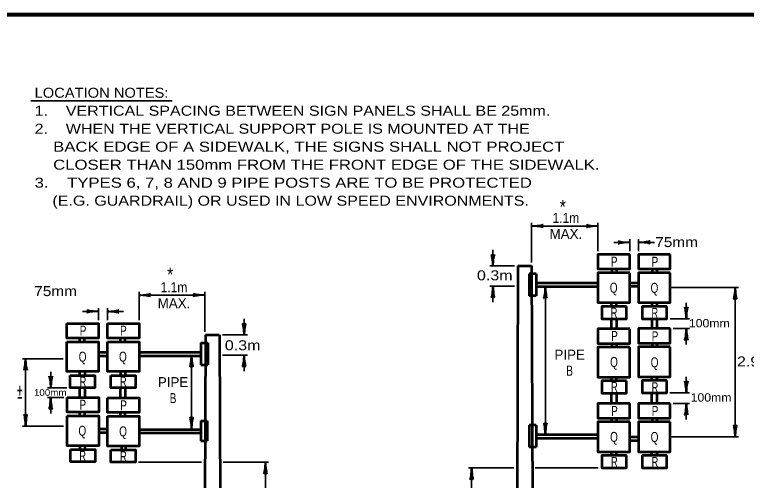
# Model space of a CAD drawing. Extents: x -274 to 582, y -298 to 246.
# Drawn here: x -65.4 to 154.4, y 100.2 to 240 of the extents above; entities that cross this region are included whole.
import ezdxf
from ezdxf.enums import TextEntityAlignment as Align

# ---------------------------------------------------------------- set-up
doc = ezdxf.new("R2010")
doc.units = 0
doc.header["$LTSCALE"] = 1.2
doc.layers.add('1', color=7, linetype='Continuous', lineweight=53)

msp = doc.modelspace()

# ---------------------------------------------------------------- linework, layer by layer
at = {"layer": '1', "lineweight": 35}
for p, q in [((-60.569, 214.078), (-18.056, 214.078)), ((89.842, 165.522), (89.842, 177.471)), ((109.785, 176.513), (89.842, 176.513)), ((109.785, 168.966), (109.785, 177.471)), ((119.321, 171.618), (114.529, 171.618)), ((119.321, 168.966), (119.321, 172.576)), ((121.978, 168.966), (121.978, 172.576)), ((126.769, 171.618), (121.978, 171.618)), ((78.241, 169.355), (78.241, 164.563)), ((84.76, 164.563), (77.282, 164.563)), ((84.76, 158.494), (77.282, 158.494)), ((78.241, 158.494), (78.241, 153.702)), ((93.996, 158.284), (93.996, 113.897)), ((-27.98, 148.24), (-27.98, 156.746)), ((-8.292, 144.796), (-8.292, 156.746)), ((131.513, 158.023), (151.957, 158.023)), ((150.999, 158.023), (150.999, 113.28)), ((-28.023, 155.787), (-8.292, 155.787)), ((-40.215, 148.24), (-40.215, 151.85)), ((-37.558, 148.24), (-37.558, 151.85)), ((136.326, 153.5), (136.326, 148.708)), ((-45.006, 150.892), (-40.215, 150.892)), ((-37.558, 150.892), (-32.766, 150.892)), ((3.522, 148.629), (3.522, 143.838)), ((131.462, 148.708), (137.284, 148.708)), ((132.407, 145.762), (137.284, 145.762)), ((136.326, 145.762), (136.326, 140.97)), ((-2.997, 143.838), (4.481, 143.838)), ((-63.006, 136.7), (-50.809, 136.7)), ((-62.135, 136.7), (-62.135, 116.476)), ((-12.29, 137.758), (-12.29, 115.671)), ((-2.997, 137.768), (4.481, 137.768)), ((3.522, 137.768), (3.522, 132.977)), ((-54.563, 132.774), (-54.563, 127.983)), ((136.326, 131.254), (136.326, 126.462)), ((-49.699, 127.983), (-55.521, 127.983)), ((131.398, 126.462), (137.284, 126.462)), ((-50.644, 125.036), (-55.521, 125.036)), ((-54.563, 125.036), (-54.563, 120.244)), ((132.407, 123.265), (137.284, 123.265)), ((136.326, 123.265), (136.326, 118.473)), ((-63.006, 116.476), (-50.752, 116.476)), ((131.449, 113.28), (151.957, 113.28)), ((-28.188, 105.611), (-9.269, 105.611)), ((-2.808, 105.611), (10.824, 105.611)), ((9.93, 105.611), (9.93, 70.015)), ((84.507, 103.928), (70.875, 103.928)), ((71.833, 103.928), (71.833, 68.332)), ((109.887, 103.928), (90.968, 103.928))]:
    msp.add_line(p, q, dxfattribs=at)
at = {"layer": '1'}
for p, q in [((85.718, 164.563), (85.452, 68.332)), ((85.718, 164.563), (89.842, 164.563)), ((89.842, 164.563), (90.241, 68.332)), ((114.005, 162.511), (114.005, 163.632)), ((115.426, 162.511), (115.426, 163.632)), ((126.197, 162.511), (126.197, 163.632)), ((127.618, 162.511), (127.618, 163.632)), ((91.237, 162.207), (89.142, 162.207)), ((89.142, 162.207), (89.142, 155.606)), ((91.237, 162.207), (91.237, 155.606)), ((109.746, 159.399), (91.237, 159.399)), ((109.746, 158.284), (91.237, 158.284)), ((122.068, 159.356), (119.411, 159.356)), ((122.068, 158.329), (119.411, 158.329)), ((91.237, 155.606), (89.142, 155.606)), ((113.845, 152.411), (113.845, 153.535)), ((115.394, 152.411), (115.394, 153.535)), ((126.037, 152.411), (126.037, 153.535)), ((127.586, 152.411), (127.586, 153.535)), ((113.877, 145.637), (113.877, 148.583)), ((115.426, 145.637), (115.426, 148.583)), ((126.037, 145.762), (126.037, 148.708)), ((127.586, 145.762), (127.586, 148.708)), ((-45.855, 141.785), (-45.855, 142.906)), ((-44.434, 141.785), (-44.434, 142.906)), ((-33.663, 141.785), (-33.663, 142.906)), ((-32.242, 141.785), (-32.242, 142.906)), ((-8.14, 143.838), (-8.345, 70.015)), ((-8.079, 143.838), (-3.955, 143.838)), ((-3.862, 143.838), (-3.556, 70.015)), ((-9.474, 141.482), (-7.379, 141.482)), ((-9.474, 141.482), (-9.474, 134.88)), ((-7.379, 141.482), (-7.379, 134.88)), ((114.005, 140.139), (114.005, 141.26)), ((115.426, 140.139), (115.426, 141.26)), ((126.133, 140.264), (126.133, 141.385)), ((127.554, 140.264), (127.554, 141.385)), ((-40.305, 138.631), (-37.648, 138.631)), ((-27.983, 138.673), (-9.474, 138.673)), ((-40.305, 137.603), (-37.648, 137.603)), ((-27.983, 137.558), (-9.474, 137.558)), ((-9.474, 134.88), (-7.379, 134.88)), ((-45.823, 131.686), (-45.823, 132.809)), ((-44.274, 131.686), (-44.274, 132.809)), ((-33.483, 131.713), (-33.483, 132.734)), ((-32.075, 131.713), (-32.075, 132.734)), ((113.845, 130.04), (113.845, 131.163)), ((115.394, 130.04), (115.394, 131.163)), ((125.973, 130.165), (125.973, 131.288)), ((127.523, 130.165), (127.523, 131.288)), ((-45.823, 125.036), (-45.823, 127.983)), ((-44.274, 125.036), (-44.274, 127.983)), ((-33.663, 124.911), (-33.663, 127.858)), ((-32.114, 124.911), (-32.114, 127.858)), ((113.874, 123.265), (113.874, 126.212)), ((115.424, 123.265), (115.424, 126.212)), ((125.973, 123.265), (125.973, 126.462)), ((127.523, 123.265), (127.523, 126.462)), ((-45.791, 119.539), (-45.791, 120.66)), ((-44.37, 119.539), (-44.37, 120.66)), ((-33.663, 119.414), (-33.663, 120.534)), ((-32.242, 119.414), (-32.242, 120.534)), ((114.002, 117.768), (114.002, 118.889)), ((115.424, 117.768), (115.424, 118.889)), ((126.133, 117.768), (126.133, 118.889)), ((127.554, 117.768), (127.554, 118.889)), ((-9.474, 118.024), (-7.569, 118.024)), ((-9.474, 118.024), (-9.474, 112.022)), ((-7.569, 118.024), (-7.569, 112.022)), ((91.237, 116.706), (89.142, 116.706)), ((89.142, 116.706), (89.142, 110.104)), ((91.237, 116.706), (91.237, 110.104)), ((-40.076, 115.618), (-37.419, 115.618)), ((-40.076, 114.59), (-37.419, 114.59)), ((-28.023, 115.471), (-9.474, 115.471)), ((-28.023, 114.457), (-9.474, 114.457)), ((109.746, 113.897), (91.237, 113.897)), ((109.746, 112.782), (91.237, 112.782)), ((121.908, 113.112), (119.252, 113.112)), ((-45.76, 109.439), (-45.76, 110.562)), ((-44.21, 109.439), (-44.21, 110.562)), ((-33.369, 110.336), (-33.369, 109.314)), ((-32.076, 110.336), (-32.076, 109.314)), ((-9.474, 112.022), (-7.569, 112.022)), ((91.237, 110.104), (89.142, 110.104)), ((121.908, 112.085), (119.252, 112.085)), ((113.842, 107.668), (113.842, 108.792)), ((115.392, 107.668), (115.392, 108.792)), ((125.973, 107.668), (125.973, 108.792)), ((127.523, 107.668), (127.523, 108.792))]:
    msp.add_line(p, q, dxfattribs=at)
at = {"layer": '1', "lineweight": 158}
msp.add_lwpolyline([(575.293, 239.961), (-216.407, 239.861), (-216.307, -286.139)], dxfattribs=at)
at = {"layer": '1'}
for points in [[(119.321, 168.008), (109.785, 168.008), (109.785, 163.632), (119.321, 163.632)], [(131.513, 168.008), (121.978, 168.008), (121.978, 163.632), (131.513, 163.632)], [(119.321, 162.511), (109.785, 162.511), (109.785, 153.535), (119.321, 153.535)], [(131.513, 162.511), (121.978, 162.511), (121.978, 153.535), (131.513, 153.535)], [(118.312, 152.411), (110.909, 152.411), (110.909, 148.708), (118.312, 148.708)], [(130.504, 152.411), (123.101, 152.411), (123.101, 148.708), (130.504, 148.708)], [(-49.75, 147.282), (-40.215, 147.282), (-40.215, 142.906), (-49.75, 142.906)], [(-37.558, 147.282), (-28.023, 147.282), (-28.023, 142.906), (-37.558, 142.906)], [(119.321, 145.637), (109.785, 145.637), (109.785, 141.26), (119.321, 141.26)], [(131.449, 145.762), (121.914, 145.762), (121.914, 141.385), (131.449, 141.385)], [(-49.75, 141.785), (-40.215, 141.785), (-40.215, 132.809), (-49.75, 132.809)], [(-37.558, 141.785), (-28.023, 141.785), (-28.023, 132.809), (-37.558, 132.809)], [(119.321, 140.139), (109.785, 140.139), (109.785, 131.163), (119.321, 131.163)], [(131.449, 140.264), (121.914, 140.264), (121.914, 131.288), (131.449, 131.288)], [(-48.741, 131.686), (-41.338, 131.686), (-41.338, 127.983), (-48.741, 127.983)], [(-36.549, 131.686), (-29.146, 131.686), (-29.146, 127.983), (-36.549, 127.983)], [(118.312, 130.04), (110.909, 130.04), (110.909, 126.337), (118.312, 126.337)], [(130.44, 130.165), (123.037, 130.165), (123.037, 126.462), (130.44, 126.462)], [(-49.686, 125.036), (-40.151, 125.036), (-40.151, 120.66), (-49.686, 120.66)], [(-37.558, 124.911), (-28.023, 124.911), (-28.023, 120.534), (-37.558, 120.534)], [(119.318, 123.265), (109.783, 123.265), (109.783, 118.889), (119.318, 118.889)], [(131.449, 123.265), (121.914, 123.265), (121.914, 118.889), (131.449, 118.889)], [(-49.686, 119.539), (-40.151, 119.539), (-40.151, 110.562), (-49.686, 110.562)], [(-37.558, 119.414), (-28.023, 119.414), (-28.023, 110.438), (-37.558, 110.438)], [(119.318, 117.768), (109.783, 117.768), (109.783, 108.792), (119.318, 108.792)], [(131.449, 117.768), (121.914, 117.768), (121.914, 108.792), (131.449, 108.792)], [(-48.677, 109.439), (-41.274, 109.439), (-41.274, 105.736), (-48.677, 105.736)], [(-36.549, 109.314), (-29.146, 109.314), (-29.146, 105.611), (-36.549, 105.611)], [(118.309, 107.668), (110.906, 107.668), (110.906, 103.966), (118.309, 103.966)], [(130.44, 107.668), (123.037, 107.668), (123.037, 103.966), (130.44, 103.966)]]:
    msp.add_lwpolyline(points, close=True, dxfattribs=at)
at = {"layer": '1', "lineweight": 40}
for centre, major_axis, ratio, start_param, end_param in [((91.187, 176.767), (-2.108, -0.211), 0.07063, 0.8650754, 3.1424706), ((91.151, 176.181), (-2.143, 0.187), 0.122415, 3.1415927, 5.386832), ((108.476, 176.844), (2.143, -0.187), 0.122415, 3.1415927, 5.386832), ((108.476, 176.844), (2.143, -0.187), 0.122415, 3.1415927, 5.386832), ((108.441, 176.259), (2.108, 0.211), 0.07063, 0.8650754, 3.1424706), ((108.441, 176.259), (2.108, 0.211), 0.07063, 0.8650754, 3.1424706), ((118.011, 171.949), (2.143, -0.187), 0.122415, 3.1415927, 5.386832), ((117.976, 171.364), (2.108, 0.211), 0.07063, 0.8650754, 3.1424706), ((123.322, 171.872), (-2.108, -0.211), 0.07063, 0.8650754, 3.1424706), ((123.287, 171.286), (-2.143, 0.187), 0.122415, 3.1415927, 5.386832), ((77.987, 165.908), (0.211, -2.108), 0.07063, 0.8650754, 3.1424706), ((78.572, 165.873), (-0.187, -2.143), 0.122415, 3.1415927, 5.386832), ((77.909, 157.184), (0.187, 2.143), 0.122415, 3.1415927, 5.386832), ((77.909, 157.184), (0.187, 2.143), 0.122415, 3.1415927, 5.386832), ((78.495, 157.149), (-0.211, 2.108), 0.07063, 0.8650754, 3.1424706), ((78.495, 157.149), (-0.211, 2.108), 0.07063, 0.8650754, 3.1424706), ((93.665, 156.974), (0.187, 2.143), 0.122415, 3.1415927, 5.386832), ((94.25, 156.939), (-0.211, 2.108), 0.07063, 0.8650754, 3.1424706), ((-26.713, 156.119), (-2.143, -0.187), 0.122415, 0.8963533, 3.1415927), ((-26.713, 156.119), (-2.143, -0.187), 0.122415, 0.8963533, 3.1415927), ((-9.637, 156.041), (2.108, -0.211), 0.07063, 3.1407148, 5.41811), ((150.667, 156.713), (0.187, 2.143), 0.122415, 3.1415927, 5.386832), ((150.667, 156.713), (0.187, 2.143), 0.122415, 3.1415927, 5.386832), ((151.253, 156.678), (-0.211, 2.108), 0.07063, 0.8650754, 3.1424706), ((151.253, 156.678), (-0.211, 2.108), 0.07063, 0.8650754, 3.1424706), ((-26.678, 155.533), (-2.108, 0.211), 0.07063, 3.1407148, 5.41811), ((-26.678, 155.533), (-2.108, 0.211), 0.07063, 3.1407148, 5.41811), ((-9.601, 155.456), (2.143, 0.187), 0.122415, 0.8963533, 3.1415927), ((136.072, 150.053), (0.211, -2.108), 0.07063, 0.8650754, 3.1424706), ((136.072, 150.053), (0.211, -2.108), 0.07063, 0.8650754, 3.1424706), ((136.657, 150.018), (-0.187, -2.143), 0.122415, 3.1415927, 5.386832), ((136.657, 150.018), (-0.187, -2.143), 0.122415, 3.1415927, 5.386832), ((-41.524, 150.56), (2.143, 0.187), 0.122415, 0.8963533, 3.1415927), ((-41.559, 151.146), (2.108, -0.211), 0.07063, 3.1407148, 5.41811), ((-36.213, 150.638), (-2.108, 0.211), 0.07063, 3.1407148, 5.41811), ((-36.248, 151.223), (-2.143, -0.187), 0.122415, 0.8963533, 3.1415927), ((3.191, 145.147), (0.187, -2.143), 0.122415, 0.8963533, 3.1415927), ((3.776, 145.182), (-0.211, -2.108), 0.07063, 3.1407148, 5.41811), ((135.994, 144.452), (0.187, 2.143), 0.122415, 3.1415927, 5.386832), ((135.994, 144.452), (0.187, 2.143), 0.122415, 3.1415927, 5.386832), ((136.58, 144.417), (-0.211, 2.108), 0.07063, 0.8650754, 3.1424706), ((136.58, 144.417), (-0.211, 2.108), 0.07063, 0.8650754, 3.1424706), ((-62.389, 135.355), (0.211, 2.108), 0.07063, 3.1407148, 5.41811), ((-62.389, 135.355), (0.211, 2.108), 0.07063, 3.1407148, 5.41811), ((-61.804, 135.39), (-0.187, 2.143), 0.122415, 0.8963533, 3.1415927), ((-61.804, 135.39), (-0.187, 2.143), 0.122415, 0.8963533, 3.1415927), ((-12.543, 136.413), (0.211, 2.108), 0.07063, 3.1407148, 5.41811), ((-11.958, 136.448), (-0.187, 2.143), 0.122415, 0.8963533, 3.1415927), ((3.268, 136.424), (0.211, 2.108), 0.07063, 3.1407148, 5.41811), ((3.854, 136.459), (-0.187, 2.143), 0.122415, 0.8963533, 3.1415927), ((-54.894, 129.292), (0.187, -2.143), 0.122415, 0.8963533, 3.1415927), ((-54.309, 129.327), (-0.211, -2.108), 0.07063, 3.1407148, 5.41811), ((136.072, 127.807), (0.211, -2.108), 0.07063, 0.8650754, 3.1424706), ((136.072, 127.807), (0.211, -2.108), 0.07063, 0.8650754, 3.1424706), ((136.657, 127.772), (-0.187, -2.143), 0.122415, 3.1415927, 5.386832), ((136.657, 127.772), (-0.187, -2.143), 0.122415, 3.1415927, 5.386832), ((-54.817, 123.691), (0.211, 2.108), 0.07063, 3.1407148, 5.41811), ((-54.231, 123.726), (-0.187, 2.143), 0.122415, 0.8963533, 3.1415927), ((135.994, 121.956), (0.187, 2.143), 0.122415, 3.1415927, 5.386832), ((135.994, 121.956), (0.187, 2.143), 0.122415, 3.1415927, 5.386832), ((136.58, 121.92), (-0.211, 2.108), 0.07063, 0.8650754, 3.1424706), ((136.58, 121.92), (-0.211, 2.108), 0.07063, 0.8650754, 3.1424706), ((-62.467, 117.785), (0.187, -2.143), 0.122415, 0.8963533, 3.1415927), ((-62.467, 117.785), (0.187, -2.143), 0.122415, 0.8963533, 3.1415927), ((-61.881, 117.821), (-0.211, -2.108), 0.07063, 3.1407148, 5.41811), ((-61.881, 117.821), (-0.211, -2.108), 0.07063, 3.1407148, 5.41811), ((-12.621, 116.98), (0.187, -2.143), 0.122415, 0.8963533, 3.1415927), ((-12.621, 116.98), (0.187, -2.143), 0.122415, 0.8963533, 3.1415927), ((-12.036, 117.015), (-0.211, -2.108), 0.07063, 3.1407148, 5.41811), ((-12.036, 117.015), (-0.211, -2.108), 0.07063, 3.1407148, 5.41811), ((93.742, 115.242), (0.211, -2.108), 0.07063, 0.8650754, 3.1424706), ((93.742, 115.242), (0.211, -2.108), 0.07063, 0.8650754, 3.1424706), ((94.328, 115.207), (-0.187, -2.143), 0.122415, 3.1415927, 5.386832), ((94.328, 115.207), (-0.187, -2.143), 0.122415, 3.1415927, 5.386832), ((150.745, 114.625), (0.211, -2.108), 0.07063, 0.8650754, 3.1424706), ((150.745, 114.625), (0.211, -2.108), 0.07063, 0.8650754, 3.1424706), ((151.33, 114.589), (-0.187, -2.143), 0.122415, 3.1415927, 5.386832), ((151.33, 114.589), (-0.187, -2.143), 0.122415, 3.1415927, 5.386832), ((9.676, 104.267), (0.211, 2.108), 0.07063, 3.1407148, 5.41811), ((9.676, 104.267), (0.211, 2.108), 0.07063, 3.1407148, 5.41811), ((10.261, 104.302), (-0.187, 2.143), 0.122415, 0.8963533, 3.1415927), ((10.261, 104.302), (-0.187, 2.143), 0.122415, 0.8963533, 3.1415927), ((71.502, 102.619), (0.187, 2.143), 0.122415, 3.1415927, 5.386832), ((72.087, 102.584), (-0.211, 2.108), 0.07063, 0.8650754, 3.1424706)]:
    msp.add_ellipse(centre, major_axis=major_axis, ratio=ratio, start_param=start_param, end_param=end_param, dxfattribs=at)

# ---------------------------------------------------------------- texts
at = {"layer": '1'}
for s, width, p in [('LOCATION NOTES:', 1.1, (-59.417, 215.02)), ('1.    VERTICAL SPACING BETWEEN SIGN PANELS SHALL BE 25mm.', 1.2, (-59.417, 209.62)), ('2.    WHEN THE VERTICAL SUPPORT POLE IS MOUNTED AT THE', 1.2, (-59.417, 204.22)), ('    BACK EDGE OF A SIDEWALK, THE SIGNS SHALL NOT PROJECT', 1.25, (-59.417, 198.82)), ('    CLOSER THAN 150mm FROM THE FRONT EDGE OF THE SIDEWALK.', 1.25, (-59.417, 193.42)), ('3.    TYPES 6, 7, 8 AND 9 PIPE POSTS ARE TO BE PROTECTED', 1.25, (-59.417, 188.02)), ('    (E.G. GUARDRAIL) OR USED IN LOW SPEED ENVIRONMENTS.', 1.2, (-59.417, 182.62))]:
    msp.add_text(s, height=3, dxfattribs=dict(at, width=width)).set_placement(p)
for s, height, width, p in [('*', 4.2, 0.85, (99.219, 180.174)), ('1.1m', 3, 0.9, (100.154, 177.468)), ('75mm', 3, 1.15, (133.411, 170.197)), ('P', 3, 0.75, (114.65, 164.323)), ('P', 3, 0.75, (126.891, 164.275)), ('*', 4.2, 0.85, (-18.686, 159.846)), ('0.3m', 3, 1.2, (78.796, 160.225)), ('75mm', 3, 1.15, (-53.111, 155.486)), ('1.1m', 3, 0.9, (-17.558, 156.657)), ('Q', 3, 0.75, (114.511, 156.506)), ('Q', 3, 0.75, (126.752, 156.458)), ('R', 3, 0.7, (114.615, 149.003)), ('R', 3, 0.7, (126.856, 148.954)), ('100mm', 2.5, 1.1, (143.228, 146.107)), ('P', 3, 0.75, (-44.866, 143.614)), ('P', 3, 0.75, (-32.755, 143.627)), ('P', 3, 0.75, (114.744, 142.038)), ('P', 3, 0.75, (126.934, 141.927)), ('0.3m', 3, 1.2, (3.064, 139.233)), ('Q', 3, 0.75, (-45.005, 135.797)), ('Q', 3, 0.75, (-32.895, 135.81)), ('Q', 3, 0.75, (114.604, 134.221)), ('Q', 3, 0.75, (126.795, 134.11)), ('2.90m', 3, 1.2, (158.235, 134.364)), ('B', 3, 0.75, (101.292, 131.596)), ('R', 3, 0.7, (-44.9, 128.293)), ('R', 3, 0.7, (-32.79, 128.306)), ('R', 3, 0.7, (114.709, 126.718)), ('+', 4.2, 0.55, (-63.857, 125.113)), ('100mm', 2, 1.1, (-54.724, 125.556)), ('R', 3, 0.7, (126.9, 126.607)), ('B', 3, 0.75, (-17.833, 123.362)), ('100mm', 2.5, 1.1, (143.761, 123.818)), ('P', 3, 0.75, (-44.953, 121.388)), ('P', 3, 0.75, (-32.707, 121.218)), ('P', 3, 0.75, (114.74, 119.541)), ('P', 3, 0.75, (126.927, 119.519)), ('Q', 3, 0.75, (-45.093, 113.571)), ('Q', 3, 0.75, (-32.847, 113.4)), ('Q', 3, 0.75, (114.6, 111.723)), ('Q', 3, 0.75, (126.787, 111.702)), ('R', 3, 0.7, (-44.988, 106.067)), ('R', 3, 0.7, (-32.742, 105.897)), ('R', 3, 0.7, (114.705, 104.22)), ('R', 3, 0.7, (126.892, 104.198))]:
    msp.add_text(s, height=height, dxfattribs=dict(at, width=width)).set_placement(p, align=Align.CENTER)
for s, height, p in [('MAX.', 3, (100.154, 172.668)), ('MAX.', 3, (-17.558, 151.857)), ('PIPE', 3, (101.292, 136.396)), ('PIPE', 3, (-17.833, 128.162)), ('-', 4.2, (-63.857, 123.349))]:
    msp.add_text(s, height=height, dxfattribs=at).set_placement(p, align=Align.CENTER)

doc.saveas('drawing.dxf')
